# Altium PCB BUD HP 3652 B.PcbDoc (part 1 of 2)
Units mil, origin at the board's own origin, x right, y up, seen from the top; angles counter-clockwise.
Board outline 2604 x 4002 mil, 2 copper layers (Top Layer, Bottom Layer); 80 components, 93 nets, 415 pads, 235 vias.
Unrouted connection lines stored in the file: 48.
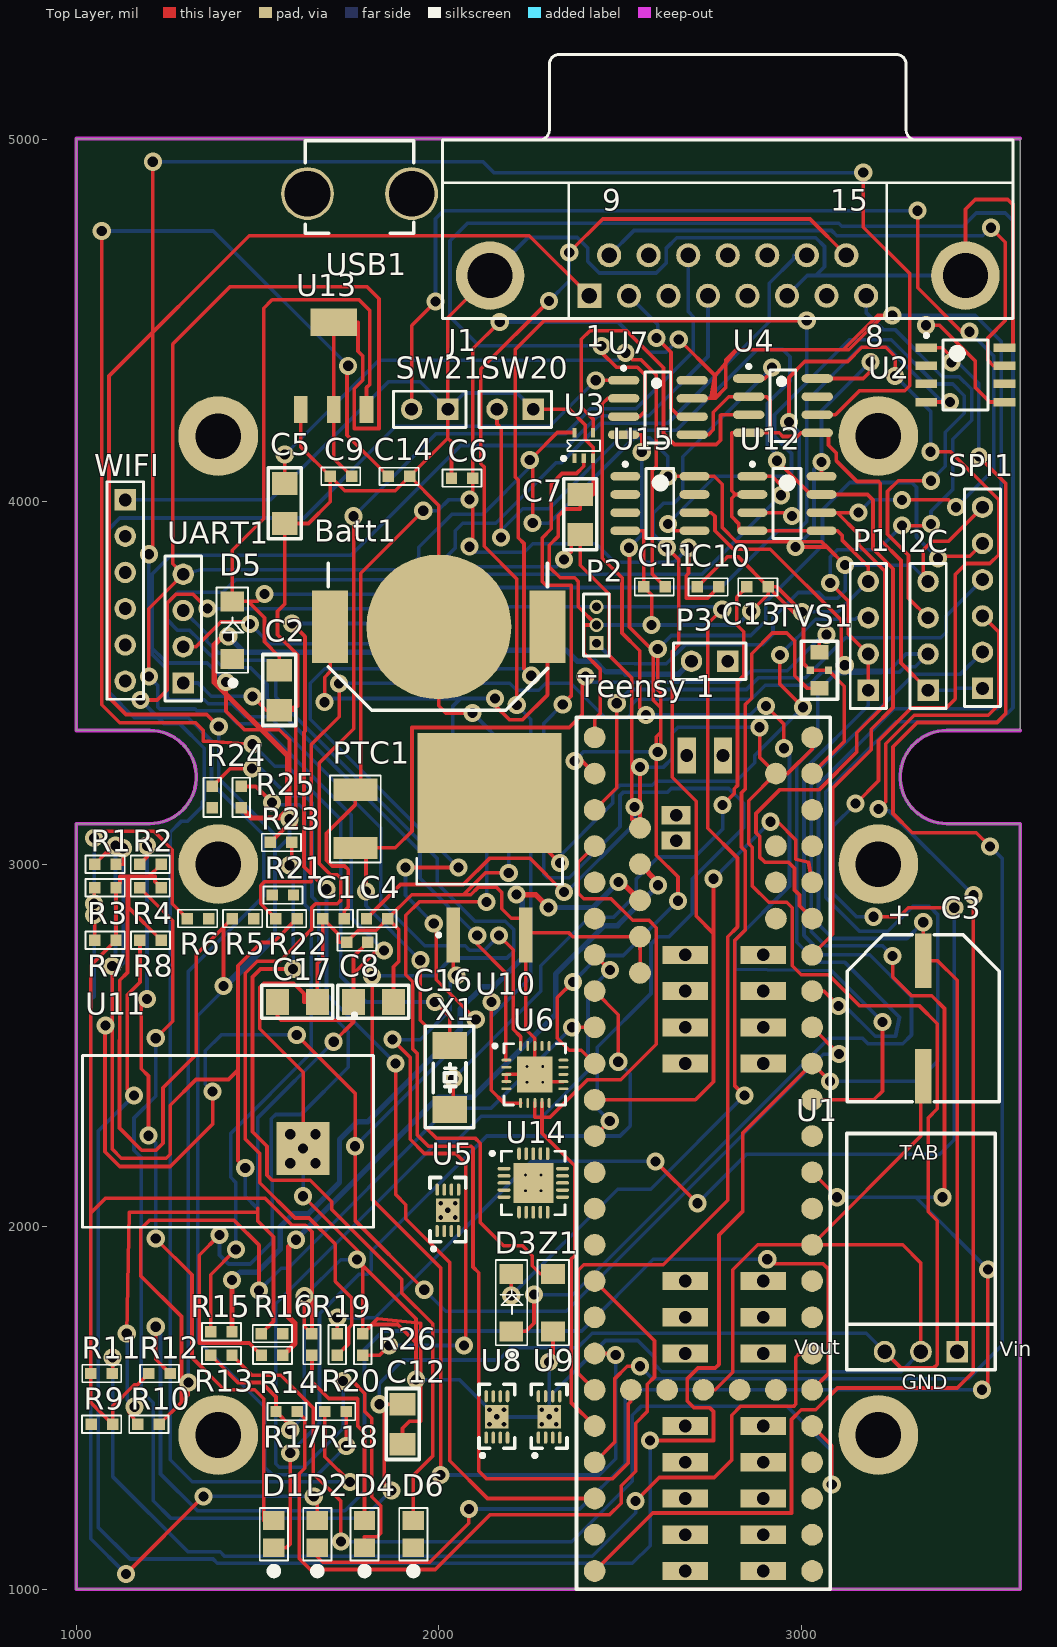
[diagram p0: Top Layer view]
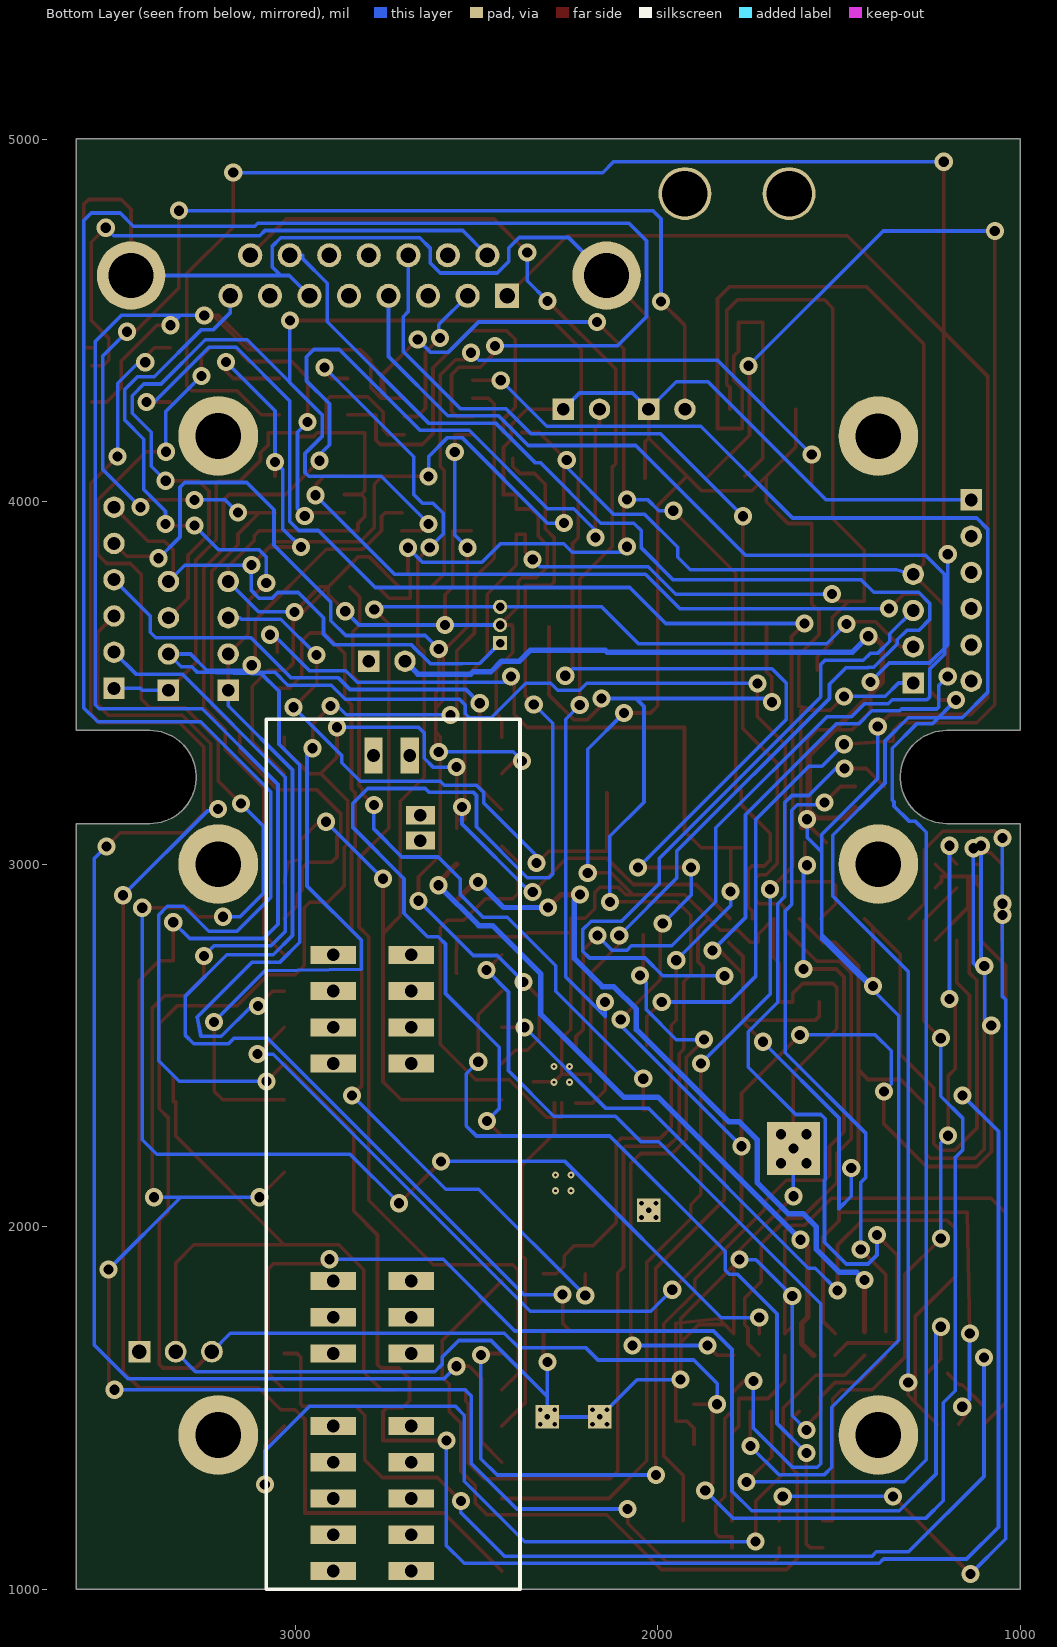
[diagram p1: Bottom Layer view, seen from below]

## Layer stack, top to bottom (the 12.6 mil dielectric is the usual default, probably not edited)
Top Solder: solder mask 0.4, Solder Resist, Dk 3.5
Top Layer: signal copper 1.4
Dielectric 1: dielectric 12.6, FR-4, Dk 4.8
Bottom Layer: signal copper 1.4
Bottom Solder: solder mask 0.4, Solder Resist, Dk 3.5

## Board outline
1000,1000 1000,3112 1202.5,3112 ccw(c1202.5,3240.5) 1202.5,3369 1000,3369 1000,5002 3604,5002 3604,3369 3401.5,3369 ccw(c3401.5,3240.5) 3401.5,3112 3604,3112 3604,1000

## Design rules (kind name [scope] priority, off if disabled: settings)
Clearance [All] p1: gap=10 ignorepadtopadclearanceinfootprint=FALSE except(0: Arc-Hole Track-Hole SMDPad-Hole THPad-Hole Via-Hole Fill-Hole Poly-Hole Region-Hole Text-Hole)
DiffPairsRouting [All] p1: maxlimit=10 minlimit=10 mostfreqgap=10 toplayer_minwidth=15 toplayer_maxwidth=15 toplayer_prefwidth=15 bottomlayer_minwidth=15 bottomlayer_maxwidth=15 bottomlayer_prefwidth=15 maxuncoupledlength=500
PolygonConnect [All] p1: connectstyle=Relief reliefconductorwidth=10 reliefentries=4 polygonreliefangle="90 Angle" airgapwidth=10
RoomDefinition "Additional Circuits - Handheld - Rev 2" [InComponentClass('Additional Circuits - Handheld - Rev 2')] p1: confinementstyle=ConfineIn formatcopy=TRUE lockcomponents=FALSE outline 3650,1060 5330,1060 5330,2760 3650,2760
RoomDefinition "Teensy 3.6 with J1939 - Handheld Rev2" [InComponentClass('Teensy 3.6 with J1939 - Handheld Rev2')] p2: confinementstyle=ConfineIn formatcopy=TRUE lockcomponents=FALSE outline 3650,2810 4895,2810 4895,3330 3650,3330
RoutingVias [All] p1: holewidth=28 width=50 viastyle="Through Hole" minholewidth=28 minwidth=50 maxholewidth=28 maxwidth=50
SolderMaskExpansion [All] p1: expansion=4
Width [All] p1: maxlimit=10 minlimit=10 preferedwidth=10
29 further rules are at their usual default settings.

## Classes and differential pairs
component class "Teensy 3.6 with J1939 - Handheld Rev2": Batt1 C7 C9 C10 C13 C14 D1 D2 D4 D6 I2C P2 R2 R3 R8 R9 R10 R11 R12 R13 R18 R19 R20 R21 R23 SW20 SW21 "Teensy 1" U2 U5 U7 U8 U9 U12 U14 UART1 X1
component class "Additional Circuits - Handheld - Rev 2": C1 C2 C3 C4 C5 C6 C8 C11 C12 C16 C17 D3 D5 J1 P1 P3 PTC1 R1 R4 R5 R6 R7 R14 R15 R16 R17 R22 R24 R25 R26 SPI1 TVS1 U1 U3 U4 U6 U10 U11 U13 U15 USB1 WIFI Z1
differential pair "USB D": +"USB D_P" -"USB D_N"
differential pair "Hst USB": +"Hst USB_P" -"Hst USB_N"

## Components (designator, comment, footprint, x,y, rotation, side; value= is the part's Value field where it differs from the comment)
Batt1 "CR1225" "Battery Clip - CR1225" 2000,3655 r180 top
C1 "0.1uF" 0603 1709.53,2850 r0 top
C2 "22uF" 1206 1560,3480 r90 top
C3 "100uF" "Elec. Cap - G" 3336.5,2574.45 r90 top
C4 "10uF" 0603 1830,2850 r0 top
C5 "10uF" 1206 1575,3995 r90 top
C6 "0.1uF" 0603 2064.53,4065 r0 top
C7 "10uF" 1206 2390,3965 r90 top
C8 "0.1uF" 0603 1775,2785 r0 top
C9 "0.1uF" 0603 1730,4070 r0 top
C10 "1uf" 0603 2742.64,3765 r180 top
C11 "0.1uF" 0603 2595,3765 r0 top
C12 "22uF" 1206 1900,1455 r90 top
C13 "18pF" 0603 2879.53,3765 r180 top
C14 "18pF" 0603 1890,4070 r180 top
C16 "22uF" 1206 1819.88,2620 r180 top
C17 "22uF" 1206 1610,2620 r180 top
D1 "Green" "0805 Polarized" 1545,1150 r90 top
D2 "Red" "0805 Polarized" 1665,1150 r90 top
D3 "ACURA107-HF" "SMA with A and K" 2200,1711 r90 top
D4 "Yellow" "0805 Polarized" 1795,1150 r90 top
D5 "ACURA107-HF" "SMA with A and K" 1430,3566 r90 top
D6 "Blue" "0805 Polarized" 1930,1150 r90 top
I2C "Header 4" HDR1X4 3350,3480 r90 top
J1 "Vehicle Interface Cable Connector" DSUB1.385-2H15 2797.16,4998.11 r0 top
P1 "Header 4" HDR1X4 3185,3480 r90 top
P2 "DNP GP-20U7 JST Header" MHDR1X3 2435,3610 r90 top
P3 "Header 2" HDR1X2 2797.17,3560 r180 top
PTC1 "PTC RESTTBLE 0.75A" 1812 1770,3125 r90 top
R1 "4.7k" 0603 1080,3000 r0 top
R2 "330" 0603 1204.53,3000 r0 top
R3 "330" 0603 1080,2935 r0 top
R4 "4.7k" 0603 1204.53,2935 r0 top
R5 "47" 0603 1459.53,2850 r0 top
R6 "47" 0603 1335.47,2850 r0 top
R7 "4.7k" 0603 1080,2790.06 r0 top
R8 "100k" 0603 1205,2790.06 r0 top
R9 "100k" 0603 1070.47,1455 r0 top
R10 "4.7k" 0603 1199.53,1455 r180 top
R11 "100k" 0603 1069.53,1595 r180 top
R12 "100k" 0603 1229.05,1595 r180 top
R13 "100k" 0603 1400,1645 r180 top
R14 "DNP" 0603 1540.47,1645 r180 top
R15 "DNP" 0603 1400,1710 r180 top
R16 "100k" 0603 1540,1705 r180 top
R17 "100k" 0603 1580.47,1490 r180 top
R18 "330" 0603 1715,1490 r180 top
R19 "330" 0603 1650,1675 r90 top
R20 "330" 0603 1720,1675 r90 top
R21 "4.7k" 0603 1569.53,2915 r180 top
R22 "4.7k" 0603 1579.53,2850 r180 top
R23 "330" 0603 1565,3060 r180 top
R24 "47" 0603 1375,3185 r90 top
R25 "47" 0603 1455,3185 r90 top
R26 "100k" 0603 1790,1675 r90 top
SPI1 "Header 6" HDR1X6 3500,3485 r90 top
SW20 "Header 2" HDR1X2 2260.71,4255 r180 top
SW21 "Header 2" HDR1X2 2025,4255 r180 top
"Teensy 1" "Teensy 3.6 Through Hole" "Teensy 3.6 Surface Mount" 2430,2050 r0 top
TVS1 "Varistor 26V" Transfeed 3050,3485 r90 top
U1 "OKI-78SR" OKI-78SR 3230,1655 r0 top
U2 "NCV7356D1R2G" ONSC-SOIC-8-751-07_V 3452.87,4350 r0 top
U3 "74AHCT1G14" SOT-353 2400,4155 r0 top
U4 "SN75HVD08DR" SOIC-SN8_N 2949.49,4265 r0 top
U5 "MCP2558" TDFN 2025,2045 r0 top
U6 "ADG1634BCPZ-REEL7" ADI-CP-20-4_N 2265,2420 r0 top
U7 "MCP2003A-E/SN" SOIC-SN8_N 2604.49,4260 r0 top
U8 "MCP2558" TDFN 2160,1475 r0 top
U9 "MCP2558" TDFN 2304.37,1475 r0 top
U10 "BTS141TC" INF-PG-TO263-3-2_N 2140,3045 r90 top
U11 "ATML-ATWINC1500-MR210PA-28" ATML-ATWINC1500-MR210PA-28_V 1580,2235 r270 top
U12 "MOCD207R2M" SOIC-8 2960.47,3995 r0 top
U13 "NCP1117LPST33" SOT-223 1619.45,4255 r0 top
U14 "MCP2515-E/ML" QFN-ML20_M 2260.71,2120.63 r0 top
U15 "ATECC508A" SOIC-8 2610,3995 r0 top
UART1 "Header 4" HDR1X4 1295,3500 r90 top
USB1 "UX60SC-MB-5S8" "USB Mini UX60S" 1781.3,4995.67 r180 top
WIFI "DNP" HDR1X6 1135,4005 r270 top
X1 "16MHz" "XTAL 2 pad" 2030,2322.83 r90 top
Z1 "SMA6J" SMA 2315,1711 r90 top

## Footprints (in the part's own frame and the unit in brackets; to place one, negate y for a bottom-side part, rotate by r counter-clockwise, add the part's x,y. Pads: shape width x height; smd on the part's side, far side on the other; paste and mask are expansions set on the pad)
0603 [mm] "0603 SMP Component with outline"
  rect 0.8x0.8 smd: 1(-0.75,0) 2(0.75,0)
  silkscreen extent -1.39,-0.61 1.36,0.61
"0805 Polarized" [mm] "Polarized 0805 with Pin 1 as Anode (+)"
  rect 1.3x1.5 smd: 1(-0.899,0) 2(1.001,0)
  silkscreen extent -2.79,-0.99 1.88,0.99
1206 [mm]
  rect 1.6x1.8 smd: 1(-1.4,0) 2(1.4,0)
  silkscreen extent -2.47,-1.16 2.5,1.15
1812 [mil] "Used for PTC Fuses from belfuse"
  rect 60x122 smd: 1(-80,0)
  rect 62x122 smd: 2(80,0)
  silkscreen extent -120,-70 120,70
ADI-CP-20-4_N [mm] "QFN, 20-Leads, Body 4x4mm, Pitch 0.5mm, Thermal Pad 2.5x2.5mm, IPC Medium Density"
  oval 0.7x0.2 smd: 1(-2,1) 2(-2,0.5) 3(-2,0) 4(-2,-0.5) 5(-2,-1) 11(2,-1) 12(2,-0.5) 13(2,0) 14(2,0.5) 15(2,1)
  oval 0.2x0.7 smd: 6(-1,-2) 7(-0.5,-2) 8(0,-2) 9(0.5,-2) 10(1,-2) 16(1,2) 17(0.5,2) 18(0,2) 19(-0.5,2) 20(-1,2)
  rect 2.5x2.5 smd: 21(0,0)
  silkscreen extent -2.92,-2.15 2.15,2.15, body extent -2,-2 2,2, height 1
ATML-ATWINC1500-MR210PA-28_V [mm] "Module, 28-Leads, Body 21.72x14.73mm, Pitch 1.016mm"
  rect 1.9x0.8 on Mech1: 1(-7.365,4.761) 2(-7.365,3.745) 3(-7.365,2.729) 4(-7.365,1.713) 5(-7.365,-2.351) 6(-7.365,-4.383) 7(-7.365,-5.399) 8(-7.365,-6.415) 9(-7.365,-7.431) 10(7.365,-5.393) 11(7.365,-4.377) 12(7.365,-3.361) 13(7.365,-2.345) 14(7.365,-1.329) 15(7.365,-0.313) 16(7.365,0.703) 17(7.365,1.719) 18(7.365,2.735) 19(7.365,3.751)
  rect 0.8x1.9 on Mech1: 20(5.465,7.431) 21(2.417,7.431) 22(1.401,7.431) 23(0.385,7.431) 24(-0.631,7.431) 25(-1.647,7.431) 26(-2.663,7.431) 27(-3.679,7.431) 28(-4.695,7.431)
  rect 3.7x3.7 hole 0.711: 29(0.485,1.161)
  silkscreen extent -8.99,-14.29 6.01,6.08, body extent -7.36,-14.29 7.36,7.43, height 3.35
"Battery Clip - CR1225" [mil] "Battery Holder Outlline for CR2032"
  rect 100x200 smd: 1(-300,0) 1(300,0)
  round 400 smd: 2(0,0)
  silkscreen extent -300,-175 305,230
DSUB1.385-2H15 [mm] "Connector; D Subminiature; 15 Position; Right Angle; Pitch 1.385 mm"
  rect 1.69x1.69 hole 1.09: 1(-9.695,-10.92)
  round 1.69 hole 1.09: 2(-6.925,-10.92) 3(-4.155,-10.92) 4(-1.385,-10.92) 5(1.385,-10.92) 6(4.155,-10.92) 7(6.925,-10.92) 8(9.695,-10.92) 9(-8.31,-8.08) 10(-5.54,-8.08) 11(-2.77,-8.08) 12(0,-8.08) 13(2.77,-8.08) 14(5.54,-8.08) 15(8.31,-8.08)
  round 4.8 hole 3.18: 16(-16.66,-9.5) 17(16.66,-9.5)
  silkscreen extent -20,-12.5 20,6
"Elec. Cap - G" [mil] "Panasonic Style Electrolytic capacitor, Can size G, 10mm diameter"
  rect 150x45 smd: 1(159.45,0) 2(-159.45,0)
  silkscreen extent -229,-210 231,210
HDR1X2 [mm] "Connector; Header; 2 Position"
  rect 1.5x1.5 hole 0.9: 1(0,0)
  round 1.5 hole 0.9: 2(2.54,0)
  silkscreen extent -1.27,-1.27 3.81,1.27
HDR1X4 [mm] "Connector; Header; 4 Position"
  rect 1.5x1.5 hole 0.9: 1(0,0)
  round 1.5 hole 0.9: 2(2.54,0) 3(5.08,0) 4(7.62,0)
  silkscreen extent -1.27,-1.27 8.89,1.27
HDR1X6 [mm] "Connector; Header; 6 Position"
  rect 1.5x1.5 hole 0.9: 1(0,0)
  round 1.5 hole 0.9: 2(2.54,0) 3(5.08,0) 4(7.62,0) 5(10.16,0) 6(12.7,0)
  silkscreen extent -1.27,-1.27 13.97,1.27
INF-PG-TO263-3-2_N [mm] "DPAK, 3-Leads, Body 10x9.25mm, Pitch 2.54mm, IPC Medium Density"
  rect 3.85x0.95 smd: 1(-6.1,2.54) 3(-6.1,-2.54)
  rect 8.4x10.1 smd: 2(3.85,0)
  silkscreen extent -6.22,-5.1 -0.75,5.1, body extent -2.55,-5.1 6.9,5.1, height 4.4
MHDR1X3 [mm] "Connector; Header; 3 Position"
  rect 1x1 hole 0.6: 1(0,0)
  round 1 hole 0.6: 2(1.27,0) 3(2.54,0)
  silkscreen extent -0.9,-0.9 3.44,0.9
OKI-78SR [mil] "Horizontal Mount SIP DC/DC Converter"
  rect 60x60 hole 40: 1(200,0)
  round 60 hole 40: 2(100,0) 3(0,0)
  silkscreen extent -105,-50 305,602
ONSC-SOIC-8-751-07_V [mm] "SOIC, 8-Leads, Body 4.9x3.9mm, Pitch 1.27mm"
  rect 1.52x0.6 smd: 1(-2.74,1.905) 2(-2.74,0.635) 3(-2.74,-0.635) 4(-2.74,-1.905) 5(2.74,-1.905) 6(2.74,-0.635) 7(2.74,0.635) 8(2.74,1.905)
  silkscreen extent -2.86,-2.45 1.58,2.88, body extent -1.95,-2.45 1.95,2.45, height 1.75
QFN-ML20_M [mm] "QFN, 20-Leads, Body 4x4mm, Pitch 0.5mm, Thermal Pad 2.8x2.8mm, IPC Low Density"
  oval 0.9x0.25 smd: 1(-2.05,1) 2(-2.05,0.5) 3(-2.05,0) 4(-2.05,-0.5) 5(-2.05,-1) 11(2.05,-1) 12(2.05,-0.5) 13(2.05,0) 14(2.05,0.5) 15(2.05,1)
  oval 0.25x0.9 smd: 6(-1,-2.05) 7(-0.5,-2.05) 8(0,-2.05) 9(0.5,-2.05) 10(1,-2.05) 16(1,2.05) 17(0.5,2.05) 18(0,2.05) 19(-0.5,2.05) 20(-1,2.05)
  rect 2.8x2.8 smd: 21(0,0)
  silkscreen extent -3,-2.22 2.22,2.22, body extent -2.07,-2.07 2.08,2.08, height 1
SMA [mil] "SMA with outline"
  rect 55x65 smd: 1(0,0) 2(159,0)
  silkscreen extent -38,-44 197,43
"SMA with A and K" [mil] "SMA with outline and Cathode Bar on Pin 2"
  rect 55x65 smd: 1(0,0) 2(159,0)
  silkscreen extent -71,-44 197,43
SOIC-8 [mm]
  oval 2.1x0.6 smd: 1(-2.425,1.905) 2(-2.425,0.635) 3(-2.425,-0.635) 4(-2.425,-1.905) 5(2.425,-1.905) 6(2.425,-0.635) 7(2.425,0.635) 8(2.425,1.905)
  silkscreen extent -2.55,-2.45 0.98,2.88
SOIC-SN8_N [mm] "SOIC, 8-Leads, Body 4.9x3.8mm, Pitch 1.27mm, IPC Medium Density"
  oval 2.2x0.6 smd: 1(-2.4,1.905) 2(-2.4,0.635) 3(-2.4,-0.635) 4(-2.4,-1.905) 5(2.4,-1.905) 6(2.4,-0.635) 7(2.4,0.635) 8(2.4,1.905)
  silkscreen extent -2.52,-2.5 0.9,2.88, body extent -2,-2.5 2,2.5, height 1.75
SOT-223 [mm]
  rect 0.95x1.9 smd: 1(0,0) 2(2.3,0) 3(4.6,0)
  rect 3.25x1.9 smd: 4(2.3,6.1)
SOT-353 [mil]
  rect 12x26 smd: 1(-25.59,-35.43) 2(0,-35.43) 3(25.59,-35.43) 4(25.59,35.43) 6(-25.59,35.43)
  silkscreen extent -61,-40 44,15
TDFN [mm] "8-Lead Plastic Dual Flat, No Lead Package (MN) – 2x3x0.75mm Body [TDFN]"
  rect 1.651x1.651 hole 0.381: 0(0,0)
  oval 0.25x0.85 smd: 1(-0.75,-1.45) 2(-0.25,-1.45) 3(0.25,-1.45) 4(0.75,-1.45) 5(0.75,1.45) 6(0.25,1.45) 7(-0.25,1.45) 8(-0.75,1.45)
  silkscreen extent -1.25,-2.83 1.25,2.3
"Teensy 3.6 Surface Mount" [mil] "32 bit Arduino Compatible Microcontroller www.pjrc.com/teensy"
  round 60 smd: 1(0,0) 2(0,100) 3(0,200) 4(0,300) 5(0,400) 6(0,500) 7(0,600) 8(0,700) 9(0,800) 10(0,900) 11(0,1000) 12(0,1100) 13(0,1200) 14(0,1300) 15(100,-500) 16(0,-100) 17(300,-500) 18(400,-500) 19(600,-300) 20(600,0) 21(600,100) 22(600,200) 23(600,300) 24(600,400) 25(600,500) 26(600,600) 27(600,700) 28(600,800) 29(600,900) 30(600,1000) 31(600,1100) 32(600,1200) 33(600,1300) 34(500,1200) 35(500,1000) 36(500,900) 37(500,800) 38(0,-200) 39(0,-300) 40(0,-400) 41(0,-500) 42(0,-600) 43(0,-700) 44(0,-800) 45(0,-900) 46(0,-1000) 47(600,-1000) 48(600,-900) 49(600,-600) 50(600,-500) 51(600,-400) 61(600,-200) 62(600,-800) 63(600,-700) 75(125,1050) 76(125,950) 77(125,850) 78(125,750) 79(125,650) 88(500,-500) 90(600,-100) 91(200,-500)
  rect 125x50 hole 35: 52(250,-200) 53(250,-300) 54(250,-400) 55(250,-600) 56(250,-700) 57(250,-800) 58(250,-900) 59(250,-1000) 60(465,-1000) 64(465,700) 65(465,600) 66(465,500) 67(465,400) 68(465,-200) 69(465,-300) 70(465,-400) 71(465,-600) 72(465,-800) 73(465,-700) 74(465,-900) 84(250,400) 85(250,500) 86(250,600) 87(250,700)
  rect 80x50 hole 35: 80(225,1085) 81(225,1015)
  rect 50x100 hole 35: 82(354,1250)
  rect 50x100 hole 35 paste+10: 83(254,1250)
  silkscreen extent -50,-1050 650,1355
Transfeed [mil] "AVX Multilayer Ceramic Transient Voltage Suppressors"
  rect 40x50 smd: 1(0,0) 2(100,0)
  rect 20x20 smd: 3(50,-25) 3(50,25)
  silkscreen extent -30,-50 130,50
"USB Mini UX60S" [mm] "Receptacle - Standard - Shell through Hole"
  round 3.7 hole 3.2: 0(-3.65,3.7) 0(3.65,3.7)
  rect 0.5x1.4 on Mech1: 1(-1.6,6.1) 2(-0.8,6.1) 3(0,6.1) 4(1.6,6.1) 5(0.8,6.1)
  silkscreen extent -3.81,0 3.81,6.48
"XTAL 2 pad" [mm] "Digikey XC1659CT-ND"
  rect 1.9x2.4 smd: 1(0,0) 2(4.5,0)
  silkscreen extent -1.27,-1.7 5.84,1.7

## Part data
Batt1: library part "CR2032 Battery Holder", "Lithium Battery Non-Rechargeable (Primary) 3V Coin, 12.5mm", Manufacturer=Linx, PartNumber=BAT-HLD-012-SMT, Supplier Part Number 1=BAT-HLD-012-SMT-ND
C1 C9 C11: library part Cap, "CAP CER 0.1UF 50V X7R 0603", Manufacturer="Murata Electronics North America", PartNumber=GRM188R71H104KA93D, Supplier Part Number 1=490-1519-1-ND
C2 C12 C16 C17: library part Cap, "22µF ±20% 25V Ceramic Capacitor X5R 1206 (3216 Metric)", Manufacturer="Murata Electronics North America", PartNumber=GRT31CR61E226ME01L, Supplier Part Number 1=490-12451-1-ND
C3: library part "Tantalum Cap_1", "Aluminum Electrolytic Capacitors Radial, Can - SMD 5000 Hrs @ 105°C", Manufacturer="Panasonic Electronic Components", PartNumber=EEE-HC1H101P, Supplier Part Number 1=P19732CT-ND
C4: library part Cap, "10µF ±20% 25V Ceramic Capacitor X5R 0603 (1608 Metric)", Manufacturer="Murata Electronics North America", PartNumber=GRT188R61E106ME13D, Supplier Part Number 1=490-12323-1-ND
C5 C7: library part Cap, "10µF ±20% 50V Ceramic Capacitor X5R 1206 (3216 Metric)", Manufacturer="Murata Electronics North America", PartNumber=GRT31CR61H106ME01L, Supplier Part Number 1=490-12457-1-ND
C6 C8: library part Cap, "CAP CER 0.1UF 50V 10% X7R 0603", Manufacturer="Murata Electronics North America", PartNumber=GRM188R71H104KA93D, Supplier Part Number 1=490-1519-1-ND
C10: library part Cap, "1µF ±20% 50V Ceramic Capacitor X5R 0603 (1608 Metric)", Manufacturer="Murata Electronics North America", PartNumber=GRT188R61H105ME13D, Supplier Part Number 1=490-12331-1-ND
C13 C14: library part Cap, "CAP CER 18PF 50V 5% NP0 0603", Manufacturer=Kemet, PartNumber=C0603C180J5GACTU, Supplier Part Number 1=399-1052-1-ND
D1: library part "LED - SMD", "LED GREEN DIFFUSED 0805 SMD", Manufacturer="OSRAM Opto Semiconductors Inc.", PartNumber="LG R971-KN-1", Supplier Part Number 1=475-1410-1-ND
D2: library part "LED - SMD", "LED RED DIFFUSED 0805 SMD", Manufacturer="OSRAM Opto Semiconductors Inc.", PartNumber="LS R976-NR-1", Supplier Part Number 1=475-1278-1-ND
D3 D5: library part "Schottky Diode", "Diode Schottky 1000V 1A Surface Mount DO-214AC (SMA)", Manufacturer="Comchip Technology", Supplier Part Number 1=641-1884-1-ND
D4 D6: library part "LED - SMD", "LED YELLOW DIFFUSED 0805 SMD", Manufacturer="OSRAM Opto Semiconductors Inc.", PartNumber="LY R976-PS-36", Supplier Part Number 1=475-2560-1-ND
I2C P1 UART1: "Header, 4-Pin"
J1: library part "D Connector 15", "Receptacle Assembly, 15 Position, Right Angle", Manufacturer="Amphenol FCI", PartNumber=D15S33E4GV00LF, Supplier Part Number 1=609-1498-ND
P2: library part MHDR1X3, "CONN HEADER PH SIDE 3POS 2MM SMD", Manufacturer=JST, PartNumber=S3B-PH-SM4-TB(LF)(SN), Supplier Part Number 1=455-1750-1-ND
P3 SW20 SW21: "Header, 2-Pin"
PTC1: library part PTC, "PTC RESTTBLE 0.75A 33V CHIP 1812", Manufacturer="Bel Fuse Inc.", PartNumber=0ZCG0075BF2B, Supplier Part Number 1=507-1765-1-ND
R1 R4 R7 R10 R21 R22: library part "Chip Resistor", "±1% 0.1W, 1/10W Chip Resistor 0603 (1608 Metric) Automotive AEC-Q200, High Voltage Thick Film", Manufacturer="Rohm Semiconductor", PartNumber=KTR03EZPF4701, Supplier Part Number 1=RHM4.7KAYCT-ND
R2 R3 R18 R19 R20 R23: library part "Chip Resistor", "330 Ohms ±1% 0.1W, 1/10W Chip Resistor 0603 (1608 Metric) Automotive AEC-Q200, High Voltage Thick Film", Manufacturer="Rohm Semiconductor", PartNumber=KTR03EZPF3300, Supplier Part Number 1=RHM330AYCT-ND
R5 R6 R24 R25: library part "Chip Resistor", "±1% 0.1W, 1/10W Chip Resistor 0603 (1608 Metric) Automotive AEC-Q200, High Voltage Thick Film", Manufacturer="Rohm Semiconductor", PartNumber=KTR03EZPF47R0, Supplier Part Number 1=RHM47AYCT-ND
R8 R9 R11 R12 R13 R16 R17 R26: library part "Chip Resistor", "±1% 0.1W, 1/10W Chip Resistor 0603 (1608 Metric) Automotive AEC-Q200, High Voltage Thick Film", Manufacturer="Rohm Semiconductor", PartNumber=KTR03EZPF1003, Supplier Part Number 1=RHM100KAYCT-ND
R14 R15: library part "Chip Resistor", "RES SMD 47 OHM 1% 1/10W 0603", Manufacturer="Panasonic Electronic Components", PartNumber=ERJ-3EKF47R0V, Supplier Part Number 1=P47.0HCT-ND
SPI1: "Header, 6-Pin"
"Teensy 1": "24 Position Header Connector 0.100\" (2.54mm) Through Hole Gold", Manufacturer="Sullins Connector Solutions", PartNumber=PPPC241LFBN-RC, Supplier Part Number 1=S7057-ND
TVS1: library part Transfeed, "34.5V 80A Varistor 1 Circuit Surface Mount 0805 (2012 Metric)", Manufacturer=AVX, PartNumber=V2AF126C600Y2EDP, Supplier Part Number 1=478-10038-1-ND
U1: library part 7805, "5V DC/DC Converter (7805 replacement)", Manufacturer="Murata Power Solutions Inc.", PartNumber=OKI-78SR-5/1.5-W36H-C, Supplier Part Number 1=811-2692-ND
U2: library part NCV7356D1G, "Single Wire CAN Transceiver, 5 to 27 V, 8-Pin SOIC, Pb-Free, Tube", Manufacturer="On Semiconductor", Supplier Part Number 1=NCV7356D1R2GOSCT-ND
U3: library part "74AHCT1G14 Inverter", "IC SCHMIT-TRIGG INV GATE SOT353", Manufacturer="Diodes Incorporated", PartNumber=74AHCT1G14SE-7, Supplier Part Number 1=74AHCT1G14SE-7DICT-ND
U4: library part "SN75HVD12D (3.3v RS485)", "IC RS485 TXRX 3/5V 8-SOIC", Manufacturer="Texas Instruments", Supplier Part Number 1=296-37893-1-ND
U5 U8 U9: library part MCP2558FD, "Microchip CAN FD Transceiver with Silent Mode", Manufacturer=Microchip, PartNumber=MCP2558FDT-H/MNY
U6: "IC SWITCH QUAD SPDT 20LFCSP", Manufacturer="Analog Devices", Supplier Part Number 1=ADG1634BCPZ-REEL7CT-ND
U7: library part MCP2003AT-E/SN, "LIN J2602 Transceiver, 8-Pin SOIC, Extended Temperature, Tape and Reel", Manufacturer=Microchip, Supplier Part Number 1=MCP2003A-E/SN-ND
U10: "Smart Low-Side Power Switch HITFET, 60 V VDS, 12 A ID, -40 to 150 degC, PG-TO263-3-2, Reel, Green", Manufacturer=Infineon, Supplier Part Number 1=BTS141TCTR-ND
U11: "SMARTCONNECT ATWINC1500B-MU-T MO", Manufacturer="Microchip Technologies", PartNumber=ATWINC1510-MR210PB1140, Supplier Part Number 1=ATWINC1510-MR210PB1140-ND
U12: library part "Optoisolator - Dual", "Optoisolator Transistor Output 2500Vrms 2 Channel 8-SO Tall", Manufacturer="Fairchild/ON Semiconductor", Supplier Part Number 1=MOCD207R2MCT-ND
U13: library part "NCP1117 2.5V", "Linear Voltage Regulator IC Positive Fixed Output 3.3V 1A SOT-223", Manufacturer="On Semiconductor", PartNumber=NCP1117LPST33T3G, Supplier Part Number 1=NCP1117LPST33T3GOSCT-ND
U14: "CAN Controller CAN 2.0 SPI Interface 20-QFN (4x4)", Manufacturer=Microchip, Supplier Part Number 1=MCP2515-E/ML-ND
U15: "Authentication Chip IC Networking and Communications 8-SOIC", Manufacturer="Microchip Technology", PartNumber=ATECC508A-SSHDA-T, Supplier Part Number 1=ATECC508A-SSHDA-TCT-ND
USB1: library part USB-Rugged, "USB - mini B USB 2.0 Receptacle Connector 5 Position Surface Mount, Right Angle; Through Hole", Manufacturer=Hirose, Supplier Part Number 1=H11589CT-ND
WIFI: library part "Header 6", "CONN HEADER FEMALE 6POS .1\" GOLD", Manufacturer="Sullins Connector Solutions", PartNumber=PPPC061LFBN-RC, Supplier Part Number 1=S7039-ND
X1: library part "Crystal Oscillator", "CRYSTAL 16MHZ 18PF SMD", Manufacturer="TXC CORPORATION", PartNumber=7A-16.000MAAJ-T, Supplier Part Number 1=887-1086-1-ND
Z1: library part "Zener - Bidirectional", "TVS DIODE 20VWM 36.8VC SMA", Manufacturer="Micro Commercial Co", PartNumber=SMA6J24CA-TP, Supplier Part Number 1=SMA6J24CA-TPMSCT-ND

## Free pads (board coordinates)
  round 220 hole 126: 0(1391.5,1425) 0(1391.5,3000) 0(1391.5,4181) 0(3212.5,1425) 0(3212.5,3000) 0(3212.5,4181.5)

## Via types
v1: diameter 50, hole 28, Top Layer to Bottom Layer, 215 vias
v2: diameter 20, hole 13, Top Layer to Bottom Layer, 12 vias
v3: diameter 19.68, hole 7.87, Top Layer to Bottom Layer, 8 vias

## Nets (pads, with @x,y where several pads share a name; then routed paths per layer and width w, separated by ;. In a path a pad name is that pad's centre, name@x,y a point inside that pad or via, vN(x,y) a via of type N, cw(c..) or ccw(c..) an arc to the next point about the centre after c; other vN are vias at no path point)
3V3: C8.2 C9.2 C16.2 C17.2 I2C.4 P2.1 R1.1 R10.2 R16.2 R22.1 SPI1.6 U3.6 U4.8 U5.5 U8.5 U9.5 U12.8 U13.2 U13.4 U14.18 U15.8 UART1.4 | length 13996.4
  Top Layer w10: R1.1@1050.47,3000 1082.47,3032 1089,3032 v1(1108,3051) ; v1(1099,2719) 1099,2214 1124,2189 1248,2189 1259,2200 1259,2335 1330,2406 1420,2406 1446,2432 ; v1(1139,1705) 1146,2040 1500,2040 ; v1(1160,1503) 1145,1488 R10.2@1170,1455 ; v1(1200,3518) 1200,3705 UART1.4@1295,3800 1266,3829 1266,4435 1424,4593 1802,4593 1835,4560 1835,4202 1766.85,4202 1766.85,4311.85 1790,4335 1790,4402 1777,4415 1777,4495.16 U13.4@1710,4495.16 U13.2@1710,4255 1710,4119.53 C9.2@1759.53,4070 ; v1(1466,2162) 1446,2182 1446,2432 ; 1500,2050 1500,2040 ; R16.2@1510.47,1705 1544,1738.53 1544,1972 1500,2016 1500,2040 ; C17.2@1554.88,2620 1554.88,2580 1565.88,2569 1753.76,2569 1764.76,2580 ; R22.1@1609.05,2850 1543.05,2784 1510,2784 1446,2720 1446,2432 ; v1(1710,2510) 1764.76,2564.76 1764.76,2580 ; C8.2@1804.53,2785 1764.76,2745.24 1764.76,2697.76 ; v1(1849,2762) 1829,2762 1764.76,2697.76 ; v1(2251,4115) v1@2259,4123 ; v1(2259,3941) v1@2259,4123 ; U3.6@2374.41,4190.43 2374.41,4191 2327,4191 v1@2259,4123 ; v1(2632,4070) U15.8@2705.47,4070 2760,4070 2782,4048 2782,3929 2821,3890 3056,3890 3071,3875 ; v1(2984.28,3875) 3071,3875 ; U4.8@3043.98,4340 3171,4340 3191,4360 v1(3191,4386) ; U12.8@3055.94,4070 v1(3055.94,4110) ; v1(3121,3825) 3071,3875 ; I2C.4@3350,3780 3350,3803.75 3336.25,3803.75 3336.25,3866.79 3360,3890.54 3405.54,3890.54 SPI1.6@3500,3985 ; 1764.76,2580 C16.2@1764.76,2620 1764.76,2697.76
  Bottom Layer w10: v1(1099,2719) 1108,2728 v1(1108,3051) ; v1(1139,1705) 1140,1704 1140,1523 v1(1160,1503) ; v1(1200,3518) 1224.99,3493.01 1224.99,3433.66 1230.33,3428.32 1327.19,3428.32 1332.51,3423 1409.63,3423 1445.63,3387 1507.56,3387 1758,3136.56 1758,2853 v1(1849,2762) ; UART1.4@1295,3800 1342.5,3812.5 1910.52,3812.5 1944.84,3846.82 1944.84,3874.43 2036.26,3965.86 2121.86,3965.86 2251,4095 v1(2251,4115) ; v1(1466,2162) 1466,2084 1500,2050 1500,2300 v1(1710,2510) ; v1(2259,3941) 2304,3941 2540,4177 2580,4177 2632,4125 v1(2632,4070) ; P2.1@2435,3610 2490.56,3554.44 2540.44,3553 2627.19,3553 2679.19,3605 2892,3605 2922,3635 2922,3680 2991.71,3749.71 3048.29,3749.71 3064,3734 3100,3734 3121,3755 3121,3800 3146,3825 ; v1(2984.28,3875) 3035,3925.72 3035,4089.06 v1(3055.94,4110) 3055.94,4250.94 v1(3191,4386) ; v1(3121,3825) 3146,3825 ; I2C.4@3350,3780 3305,3825 3146,3825
5V0: "Teensy 1.33" "Teensy 1.34" "Teensy 1.75" C2.2 C4.1 C7.1 C12.2 D5.2 R4.1 U1.3 U5.3 U8.3 U9.3 U13.3 | length 12044.6
  Top Layer w10: R4.1@1175,2935 1266,2844 1266,2567 v1(1219,2520) ; v1(1519,3745) 1499,3725 1474,3725 ; C2.2@1560,3535.12 1560,3572.72 1519,3613.72 1519,3680 1474,3725 ; C4.1@1800.47,2850 1894.47,2944 2067.71,2944 2139.71,3016 2252,3016 v1(2345,2923) ; U13.3@1800.55,4255 1800.55,4315 1810,4324.45 1810,4527 1780,4557 1540,4557 1517,4534 1517,3953 1430,3866 D5.2@1430,3725 1474,3725 ; v1(1836,1510.12) v1@1849,1510.12 ; v1(1869,1272) 1849,1292 v1@1849,1510.12 ; C12.2@1900,1510.12 v1@1849,1510.12 ; v1(2345,3841) 2365,3861 2365,3909.88 C7.1@2390,3909.88 2390,3825 2470,3745 2470,3576 2532,3514 v1@2532,3158 ; v1(2540,3158) v1@2532,3158 ; 2555,3100 2555,3123 ; v1(2555,3268) 2555,3123 ; v1(2885,3378) 2885,3295 2930,3250 ; 3030,3350 3030,3318 2962,3250 2930,3250 ; U1.3@3230,1655 3275,1610 3365,1610 3375,1620 3375,2016 3350,2041 3350,2299.93 3375,2324.93 3375,2560 3325,2610 3160,2610 3075,2695 3000,2695 2975,2720 2975,2880 2960,2895 2910,2895 2865,2940 2865,3047 2855,3057 2855,3175 2930,3250 ; v1@2532,3158 2532,3123 2555,3123
  Bottom Layer w10: v1(1219,2520) 1219,2360 1159,2300 1159,2211 1179,2191 1179,1547 1212,1514 1212,1244 1260,1196 1793,1196 v1(1869,1272) ; v1(1519,3745) 1950.52,3745 2026.52,3821 2325,3821 v1(2345,3841) ; v1(1836,1510.12) 1836,1567.12 1900.88,1632 2165,1632 2199.37,1666.37 2383.74,1666.37 2423.37,1706 3179,1706 U1.3@3230,1655 ; v1(2345,2923) 2352,2923 2540,3111 v1(2540,3158) ; v1(2555,3268) 2620,3268 2644,3292 2644,3362 2660,3378 v1(2885,3378)
A6: J1.1 R18.1 | length 5411.5
  Top Layer w10: v1(1393,3380) 1360,3413 1137,3413 1090,3460 1090,4347 1477,4734 2249.66,4734 J1.1@2415.47,4568.19 ; v1(1744.53,1394.53) R18.1@1744.53,1490
  Bottom Layer w10: v1(1393,3380) 1393,3236.64 1548,3081.64 1548,2794.71 1335,2581.71 1335,1687.02 1520,1502.02 1520,1336 1540,1316 1666,1316 v1(1744.53,1394.53)
A7: J1.11 R20.1 | length 4128.7
  Top Layer w10: R20.1@1720,1645.47 1751,1676.47 1751,1720 1760,1729 1760,1803 1714,1849 1714,1952 1642,2024 1603.37,2024 1506,2121.37 1506,2202 1466,2242 1466,2699 1499,2732 1561,2732 1649,2820 1649,2880 1660,2891 1720,2891 1730,2901 1730,2961 1720,2971 1701,2971 1670,3002 1670,3279 1765,3374 v1(1765,3960)
  Bottom Layer w10: v1(1765,3960) 1993,4188 2350.4,4188 2419.4,4257 2544.95,4257 2702.32,4414.37 2702.32,4510.39 2688.11,4524.61 J1.11@2688.11,4680
CAN0H: J1.13 U5.7
CAN0L: J1.12 U5.6
CAN0RX: "Teensy 1.9" U5.4
CAN0TX: "Teensy 1.10" U5.1
"CAN1 Switch": "Teensy 1.11" U6.8 U6.19 | length 1182.5
  Top Layer w10: U6.8@2265,2341.26 2265,2302 2307,2302 2410,2405 2502,2405 2600,2503 2600,2825 2580,2845 2535,2845 2475,2905 2400,2905 2385,2920 2385,3005 2430,3050
CAN1H: J1.5 U8.7
CAN1L: J1.10 U8.6
CAN1RX: "Teensy 1.48" U8.4
CAN1TX: "Teensy 1.47" U8.1
CAN2H: J1.3 U6.7 U9.7
CAN2H/J1708+: J1.15 U6.6 | length 3534.6
  Top Layer w10: v1(2145,2620) 2145,2376 2180,2341 2225.63,2341 U6.6@2225.63,2341.26 ; v1(2215,3439) 2215,3787 2125,3877 2125,4096 2116,4105 2116,4366 v1(2304,4554) ; v1(2360,4688) 2452,4780 3024.33,4780 J1.15@3124.33,4680
  Bottom Layer w10: v1(2145,2620) 2145,2580 2254,2689 2254,3400 v1(2215,3439) ; v1(2304,4554) 2360,4610 v1(2360,4688)
CAN2L: J1.4 U6.20 U9.6 | length 3976.3
  Top Layer w10: v1(2166,2803) 2205,2764 2205,2545 2225.63,2524.37 U6.20@2225.63,2498.74
  Bottom Layer w10: v1(2166,2803) 2126,2763 2084.92,2763 2073,2774.92 1961.08,2774.92 1839.91,2896.09 1839.91,3100.33 1533.25,3407 1465.63,3407 1429.63,3443 1363.66,3443 1353,3453.66 1257.34,3453.66 1250,3461 1250,3538 1209,3579 1209,3800 1261,3852 1757.62,3852 2060.62,4155 2357.4,4155 2439.4,4237 2579,4237 2742.64,4400.64 J1.4@2742.64,4568.19
CAN2L/J1708-: J1.14 U6.1 | length 3971.4
  Top Layer w10: v1(2106,2803) 2106,2779 2185,2700 2185,2459.37 U6.1@2186.26,2459.37
  Bottom Layer w10: v1(2106,2803) 1948,2961 1948,3035.42 1526,3457.42 1526,3496.5 1480,3542.5 1420,3542.5 1419.5,3543 1403.71,3543 1339,3607.71 1339,3618.97 1312.97,3645 1280,3645 1250,3675 1250,3720 1280,3750 1404,3750 1439,3785 1957.79,3785 2045,3872.21 2045,3920 2066,3941 2157,3941 2324,4108 2338.68,4108 2447.68,4217 2632.41,4217 2912,4496.59 2912,4603 2980,4671 2980,4680 J1.14@3015.28,4680
CAN2RX: U9.4 U14.20
CAN2TX: U9.1 U14.19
